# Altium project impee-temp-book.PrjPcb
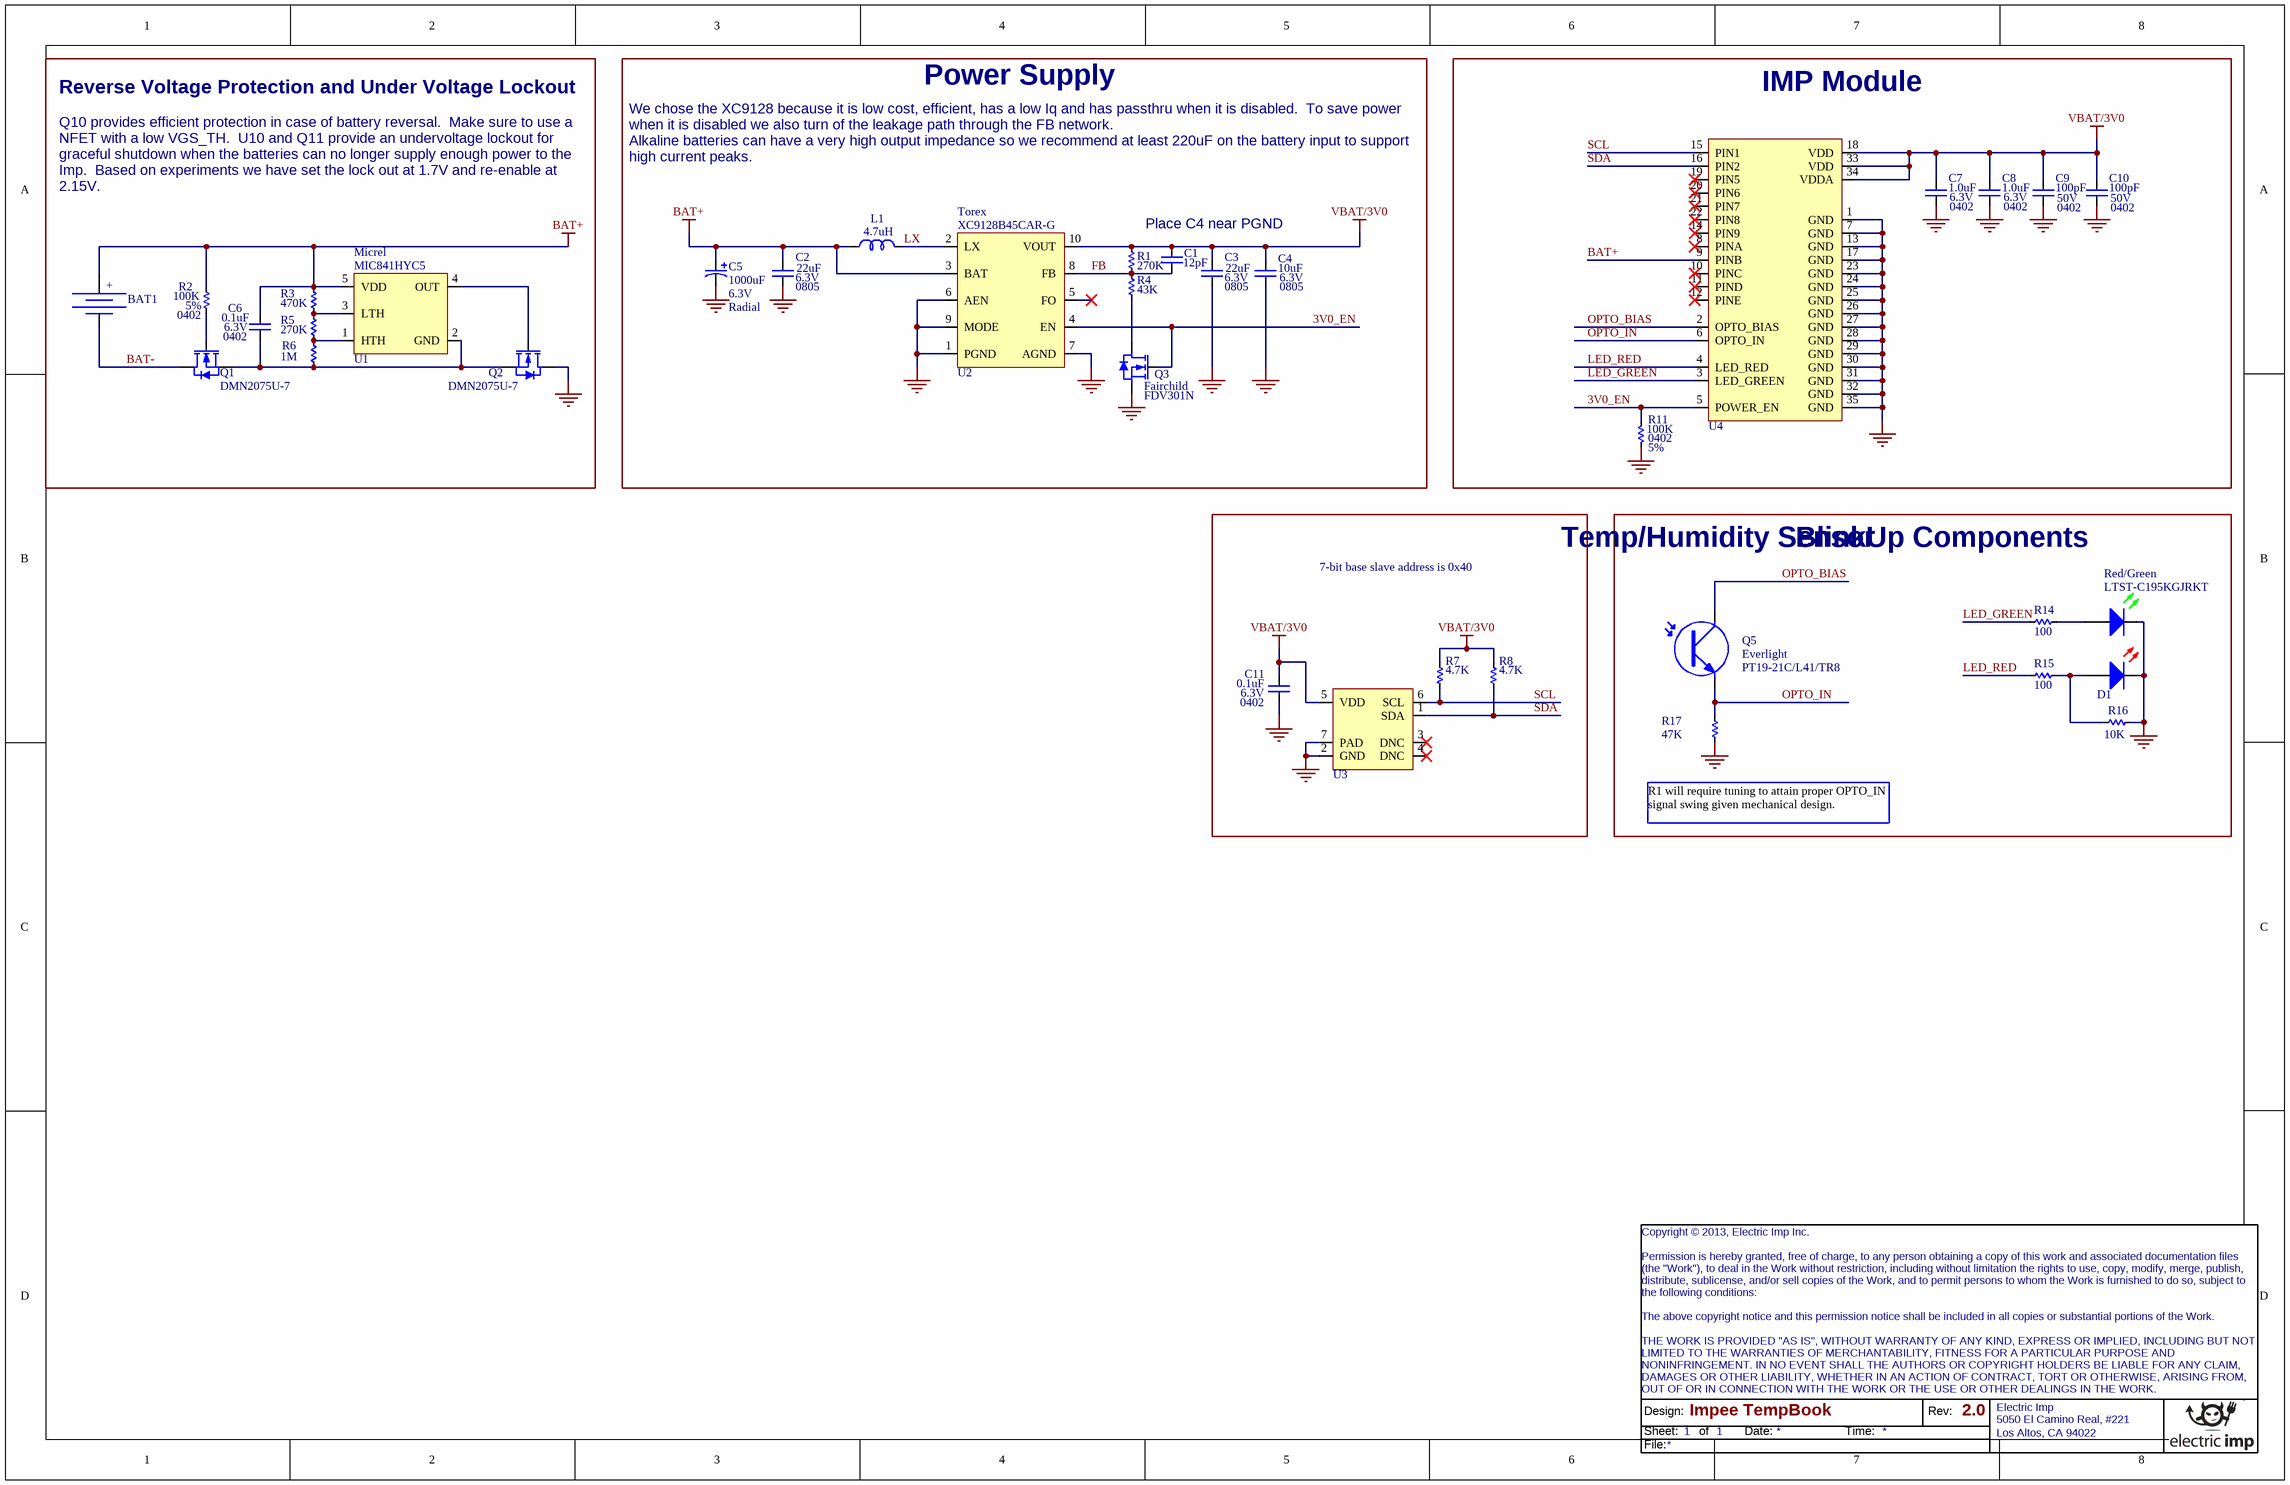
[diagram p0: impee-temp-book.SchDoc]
1 sheet, 35 parts. Net scope: global (net labels, ports and power ports of the same name join across sheets).
Board file: impee-temp-book.PcbDoc

## Sheet impee-temp-book.SchDoc: Impee TempBook
size Tabloid; Revision: 2.0; SheetNumber: 1; SheetTotal: 1; PageSetup: Record=PageOptions¦CenterHorizontal=True¦CenterVertical=True¦PrintScale=0.62¦XCorrection=1.00¦YCorrection=1.00¦PrintKind=0¦BorderSize=5000000¦LeftOffset=0¦BottomOffset=0¦Orientation=2¦PaperLength=1000¦PaperWidth=1000¦Scale=100¦PaperSource=276¦PrintQuality=600¦MediaType=1¦DitherType=10¦PaperKind=Letter 8.5"x11" 22x28cm¦PrintScaleMode=1

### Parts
BAT1  BATTERY  [12BH423-GR]  (value not drawn)
C1  value 12pF  [CAPC1005X07N]  (hidden comment: Ceramic Capacitor)
C2  value 22uF  Voltage: 6.3V  Package: 0805  [CAPC2012X14N]  (hidden comment: Ceramic Capacitor)
C3  value 22uF  Voltage: 6.3V  Package: 0805  [CAPC2012X14N]  (hidden comment: Ceramic Capacitor)
C4  value 10uF  Voltage: 6.3V  Package: 0805  [CAPC2012X14N]  (hidden comment: Ceramic Capacitor)
C5  value 1000uF  Voltage: 6.3V  Package: Radial  [CAPAE80X110-RADIAL-RIGHTANGLE]  (hidden comment: Polarized Capacitor)
C6  value 0.1uF  Voltage: 6.3V  Package: 0402  [CAPC1005X07N]  (hidden comment: Ceramic Capacitor)
C7  value 1.0uF  Voltage: 6.3V  Package: 0402  [CAPC1005X07N]  (hidden comment: Ceramic Capacitor)
C8  value 1.0uF  Voltage: 6.3V  Package: 0402  [CAPC1005X07N]  (hidden comment: Ceramic Capacitor)
C9  value 100pF  Voltage: 50V  Package: 0402  [CAPC1005X07N]  (hidden comment: Ceramic Capacitor)
C10  value 100pF  Voltage: 50V  Package: 0402  [CAPC1005X07N]  (hidden comment: Ceramic Capacitor)
C11  value 0.1uF  Voltage: 6.3V  Package: 0402  [CAPC1005X07N]  (hidden comment: Ceramic Capacitor)
D1  Color: Red/Green  Manufacturer Part Number: LTST-C195KGJRKT  [LED1616X07N-REDGREEN]  (hidden comment: LED Red and Green)
L1  value 4.7uH  [INDP6060X28N]  (hidden comment: Inductor)
Q1  Manufacturer Part Number: DMN2075U-7  [SOT95P300X130-3N]  (hidden comment: N-Channel MOSFET)
Q2  Manufacturer Part Number: DMN2075U-7  [SOT95P300X130-3N]  (hidden comment: N-Channel MOSFET)
Q3  Manufacturer: Fairchild  Manufacturer Part Number: FDV301N  [SOT95P300X130-3N]  (hidden comment: N-Channel MOSFET)
Q5  Manufacturer: Everlight  Manufacturer Part Number: PT19-21C/L41/TR8  [PHOTOTRANS1608X8]  (hidden comment: PHOTOTRANSISTOR)
R1  value 270K  [RESC1005X04N]  (hidden comment: Resistor)
R2  value 100K  Package: 0402  Tolerance: 5%  [RESC1005X04N]  (hidden comment: Resistor)
R3  value 470K  [RESC1005X04N]  (hidden comment: Resistor)
R4  value 43K  [RESC1005X04N]  (hidden comment: Resistor)
R5  value 270K  [RESC1005X04N]  (hidden comment: Resistor)
R6  value 1M  [RESC1005X04N]  (hidden comment: Resistor)
R7  value 4.7K  [RESC1005X04N]  (hidden comment: Resistor)
R8  value 4.7K  [RESC1005X04N]  (hidden comment: Resistor)
R11  value 100K  Package: 0402  Tolerance: 5%  [RESC1005X04N]  (hidden comment: Resistor)
R14  value 100  [RESC1005X04N]  (hidden comment: Resistor)
R15  value 100  [RESC1005X04N]  (hidden comment: Resistor)
R16  value 10K  [RESC1005X04N]  (hidden comment: Resistor)
R17  value 47K  [RESC1005X04N]  (hidden comment: Resistor)
U1  Manufacturer: Micrel  Manufacturer Part Number: MIC841HYC5  [SOT65P200X125-5N]  (hidden comment: MIC841)
U2  Manufacturer: Torex  Manufacturer Part Number: XC9128B45CAR-G  [MSOP50P490X116-10N]  (hidden comment: XC9128)
U3  SI7021  [Si7021]  (value not drawn)
U4  imp module  [IMP_MODULE]  (value not drawn)

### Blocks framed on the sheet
Reverse Voltage Protection and Under Voltage Lockout: BAT1 C6 Q1 Q2 R2 R3 R5 R6 U1
Power Supply: C1-C5 L1 Q3 R1 R4 U2
IMP Module: C7-C10 R11 U4
Temp/Humidity Sensor: C11 R7 R8 U3
BlinkUp Components: D1 Q5 R14-R17

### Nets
BAT+: BAT1.+ C2.2 C5.1 C6.2 L1.1 R2.2 R3.1 U1.5(VDD) U2.3(BAT) U4.9(PINB)
GND: C2.1 C3.1 C4.1 C5.2 C7.1 C8.1 C9.1 C10.1 C11.1 D1.KG D1.KR Q2.3(D) Q3.2(S) R11.1 R16.1 R17.1 U2.1(PGND) U2.6(AEN) U2.7(AGND) U2.9(MODE) U3.2(GND) U3.7(PAD) U4.1(GND) U4.7(GND) U4.13(GND) U4.17(GND) U4.23(GND) U4.24(GND) U4.25(GND) U4.26(GND) U4.27(GND) U4.28(GND) U4.29(GND) U4.30(GND) U4.31(GND) U4.32(GND) U4.35(GND)
VBAT/3V0: C1.2 C3.2 C4.2 C7.2 C8.2 C9.2 C10.2 C11.2 R1.2 R7.1 R8.1 U2.10(VOUT) U3.5(VDD) U4.18(VDD) U4.33(VDD) U4.34(VDDA)
3V0_EN: Q3.1(G) R11.2 U2.4(EN) U4.5(POWER_EN)
BAT-: BAT1.- Q1.3(D)
FB: C1.1 R1.1 R4.2 U2.8(FB)
LED_GREEN: R14.2 U4.3(LED_GREEN)
LED_RED: R15.2 U4.4(LED_RED)
LX: L1.2 U2.2(LX)
OPTO_BIAS: Q5.C U4.2(OPTO_BIAS)
OPTO_IN: Q5.E R17.2 U4.6(OPTO_IN)
SCL: R7.2 U3.6(SCL) U4.15(PIN1)
SDA: R8.2 U3.1(SDA) U4.16(PIN2)
NetC6_1: C6.1 Q1.2(S) Q2.2(S) R6.1 U1.2(GND)
NetD1_AG: D1.AG R14.1
NetD1_AR: D1.AR R15.1 R16.2
NetQ1_1: Q1.1(G) R2.1
NetQ2_1: Q2.1(G) U1.4(OUT)
NetQ3_3: Q3.3(D) R4.1
NetR3_2: R3.2 R5.1 U1.3(LTH)
NetR5_2: R5.2 R6.2 U1.1(HTH)

Not connected (* = marked no-connect by the designer): U2 5(FO)*; U3 3(DNC)* 4(DNC)*; U4 8(PINA)* 10(PINC)* 11(PIND)* 12(PINE)* 14(PIN9)* 19(PIN5)* 20(PIN6)* 21(PIN7)* 22(PIN8)*

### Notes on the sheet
- We chose the XC9128 because it is low cost, efficient, has a low Iq and has passthru when it is disabled.  To save power when it is disabled we also turn of the leakage path through the FB network.
  Alkaline batteries can have a very high output impedance so we recommend at least 220uF on the battery input to support high current peaks.
- Q10 provides efficient protection in case of battery reversal.  Make sure to use a NFET with a low VGS_TH.  U10 and Q11 provide an undervoltage lockout for graceful shutdown when the batteries can no longer supply enough power to the Imp.  Based on experiments we have set the lock out at 1.7V and re-enable at 2.15V.
- Place C4 near PGND
- 7-bit base slave address is 0x40
- (near R17) R1 will require tuning to attain proper OPTO_IN signal swing given mechanical design.

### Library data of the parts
BAT1 = BAT00002: 2xAAA Series Battery Holder with Through-Hole PCB Mount; Manufacturer: Eagle Plastic Devices; Voltage (Min): 1.6V; Voltage (Nominal): 3.0V; Voltage (Max): 3.2V
C1 = CAPC00041: CAP,C0G,12pF,5%,50V,0402#; Manufacturer: Yageo; Manufacturer Part Number: CC0402JRNPO9BN120
C2 C3 = CAPC00039: CAP,X5R,22uF,10%,6.3V,0805,#; Manufacturer: TDK; Manufacturer Part Number: C2012X5R0J226K/1.25
C4 = CAPC00036: CAP,X5R,10uF,10%,6.3V,0805,#; Manufacturer: Yageo; Manufacturer Part Number: CC0805KKX5R5BB106
C5 = CAPC00052: CAP,ALUM,1000uF,20%,6.3V, 8mm DIA,RADIAL#; Manufacturer: Kemet; Manufacturer Part Number: ESK108M6R3AG3AA
C6 C11 = CAPC00002: CAP,X5R,0.1uF,10%,6.3V, 0402,#; Manufacturer: TDK; Manufacturer Part Number: C1005X5R0J104K
C7 C8 = CAPC00005: CAP,X5R,1.0uF,10%,6.3V, 0402,#; Manufacturer: Murata; Manufacturer Part Number: GRM155R60J105KE19D
C9 C10 = CAPC00043: CAP,C0G,100pF,5%,50V,0402; Manufacturer: Yageo; Manufacturer Part Number: CC0402JRNPO9BN101
D1 = LED00012: LED, Red and Green, 2/2V, 631/571nm, 25/35mcd, SMT; Manufacturer: Liteon; Millicandela Rating (min): 25mcd, 35mcd; Voltage - Forward (Vf) Typ: 2V, 2V; Current - Test: 20mA; Wavelength - Dominant: 631nm, 571nm; Wavelength - Peak: 639nm, 574nm; Viewing Angle: 130°; Lens Type: Clear
L1 = IND00007: IND, 4.7uH, 20%, 2.7A Isat, 403 mOhm, 6028; Manufacturer: Taiyo Yuden; Manufacturer Part Number: NR6028T4R7M
Q1 Q2 = NFET00004: NFET, 20V, 4.2A, SOT23; Manufacturer: Diodes Incorporated; Rds On (Max) @ Id, Vgs: 45 mOhm @ 3.1A, 2.5V; Vgs(th) (Max) @ Id: 1.0V @ 250uA; Power - Max: 800mW
Q3 = NFET00003: NFET, 25V, 220mA, SOT23; Rds On (Max) @ Id, Vgs: 5 ohm @ 200mA, 2.7V; Vgs(th) (Max) @ Id: 1.06V @ 250uA; Power - Max: 350mW
Q5 = PHOTO00011: Phototrans, Clear, Top View, 940nm, 0.4V, 0.6mA, 0603
R1 = RES00040: RES,270K,1%,0.063W,0402; Manufacturer: Yageo; Manufacturer Part Number: RC0402FR-07270KL
R2 R11 = RES00001: RES,100k,5%,0.063W,0402,#; Manufacturer: Samsung; Manufacturer Part Number: RC1005J104CS
R3 = RES00009: RES,470k,5%,0.063W,0402; Manufacturer: Yageo; Manufacturer Part Number: RC0402JR-07470KL
R4 = RES00041: RES,43K,1%,0.063W,0402; Manufacturer: Yageo; Manufacturer Part Number: RC0402FR-0743KL
R5 = RES00015: RES,270K,5%,0.063W,0402; Manufacturer: Yageo; Manufacturer Part Number: RC0402JR-07270KL
R6 = RES00010: RES,1M,5%,0.063W,0402,#; Manufacturer: Yageo; Manufacturer Part Number: RC0402JR-071ML
R7 R8 = RES00038: RES,4.7K,1%,0.1W,0402,#; Manufacturer: Yageo; Manufacturer Part Number: RC0402FR-134K7L; Power: 0.063W
R14 R15 = RES00024: RES,100 Ohm,1%,0.063W,0402,#; Manufacturer: Yageo; Manufacturer Part Number: RC0402FR-07100RL; BOMOPTION: DNS
R16 = RES00006: RES,10k,5%,0.063W,0402,#; Manufacturer: Stackpole; Manufacturer Part Number: RMCF0402JT10K0
R17 = RES00008: RES,47k,5%,0.063W,0402; Manufacturer: Yageo; Manufacturer Part Number: RC0402JR-0747KL; BOMOPTION: DNS
U1 = IC00032: IC, Comparator with Reference and Programmable Hysteresis, SOT-353
U2 = IC00026: IC, DC/DC boost,Adj Output,6Vin,500mA,MSOP10
U3 = IC00157: IC, Sensor, Temp+Humidity, Si7021, DFN6; Manufacturer: Silicon Labs
U4 = MOD00002: Module, Electric Imp Solder Down with Antenna; Manufacturer Part Number: IMP002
